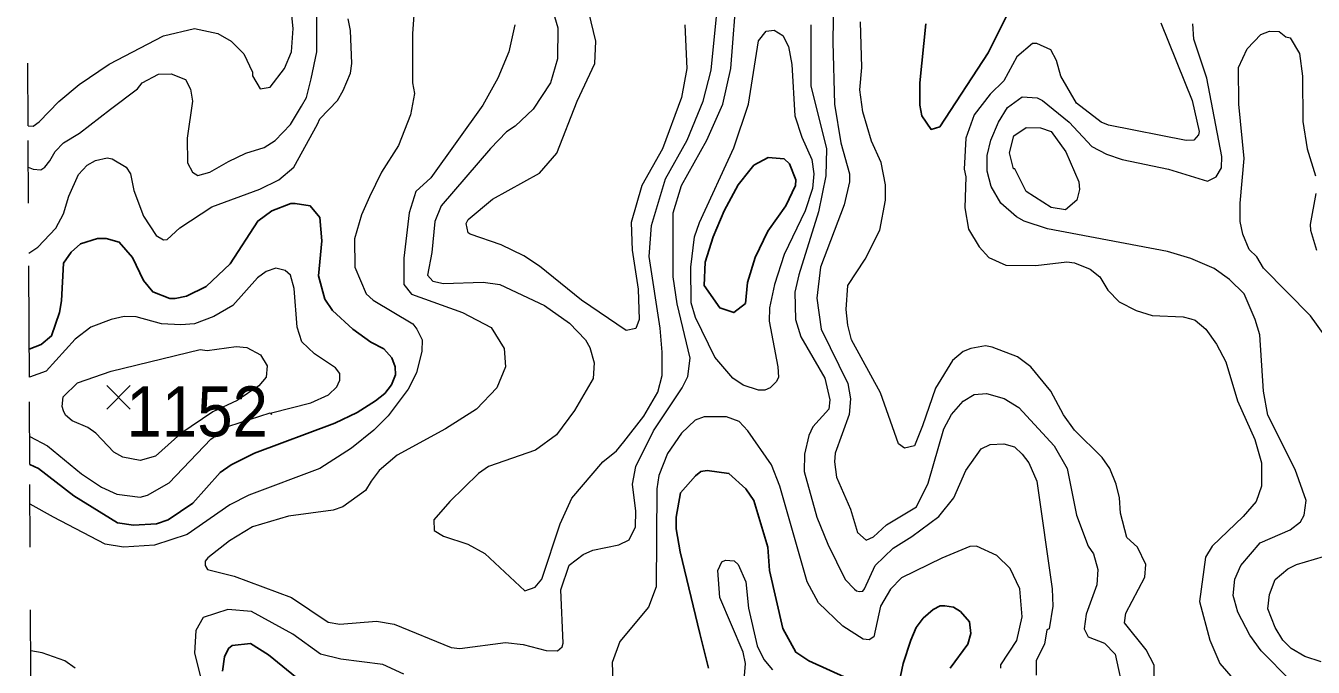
# Model space of a CAD drawing. Extents: x 423 to 448.8, y 7456.3 to 7484.
# Drawn here: x 423.048 to 425.103, y 7471.525 to 7472.549 of the extents above; entities that cross this region are included whole.
import ezdxf
from ezdxf.enums import TextEntityAlignment as Align

# ---------------------------------------------------------------- set-up
doc = ezdxf.new("R2010")
doc.units = 0
doc.header["$LTSCALE"] = 0.032
doc.linetypes.add('SHORT_DASHED', pattern=[2.7, 1.5, -1.2])
for name, color, linetype, lineweight in [('1', 7, 'Continuous', 25), ('2', 7, 'Continuous', 13), ('21', 7, 'Continuous', 25), ('22', 7, 'SHORT_DASHED', 13)]:
    doc.layers.add(name, color=color, linetype=linetype, lineweight=lineweight)
doc.layers.add('61', color=7, linetype='Continuous')

msp = doc.modelspace()

# ---------------------------------------------------------------- linework, layer by layer
at = {"layer": '1'}
for points in [[(424.6197, 7472.5766), (424.5841, 7472.5054), (424.5067, 7472.3871), (424.4928, 7472.3832), (424.4781, 7472.4049), (424.475, 7472.4219), (424.475, 7472.4575), (424.4843, 7472.5518)], [(423.0536, 7472.0326), (423.0727, 7472.0398), (423.089, 7472.0537), (423.1021, 7472.0908), (423.1052, 7472.1094), (423.1083, 7472.1697), (423.1207, 7472.1875), (423.1354, 7472.2006), (423.1625, 7472.2091), (423.1764, 7472.2091), (423.1973, 7472.203), (423.2181, 7472.179), (423.2359, 7472.1419), (423.2506, 7472.1241), (423.2777, 7472.1132), (423.2862, 7472.1132), (423.3048, 7472.1171), (423.3357, 7472.1326), (423.3744, 7472.1689), (423.4185, 7472.237), (423.4409, 7472.2533), (423.4711, 7472.2648), (423.478, 7472.2648), (423.502, 7472.261), (423.5175, 7472.2424), (423.5206, 7472.2053), (423.5152, 7472.1496), (423.5252, 7472.1125), (423.5376, 7472.0939), (423.5701, 7472.0645), (423.5987, 7472.0436), (423.6196, 7472.0328), (423.6322, 7472.0188), (423.6373, 7472.0042), (423.6382, 7471.9913), (423.6319, 7471.9756), (423.6211, 7471.9617), (423.6064, 7471.95), (423.5771, 7471.9315), (423.5415, 7471.9145), (423.4131, 7471.8665), (423.376, 7471.848), (423.3581, 7471.8356), (423.3148, 7471.7868), (423.2754, 7471.7598), (423.2568, 7471.7536), (423.2197, 7471.7513), (423.1942, 7471.7551), (423.1246, 7471.7985), (423.0681, 7471.8418), (423.0545, 7471.8482)], [(424.2321, 7471.7165), (424.2097, 7471.7907), (424.1973, 7471.8093), (424.1703, 7471.834), (424.1355, 7471.8387), (424.1254, 7471.8371), (424.1169, 7471.8302), (424.0929, 7471.8031), (424.086, 7471.7644), (424.086, 7471.7459), (424.0922, 7471.7088), (424.1238, 7471.5788), (424.1378, 7471.5231)], [(424.3598, 7471.5069), (424.2979, 7471.5347), (424.277, 7471.5486), (424.2561, 7471.5866), (424.2352, 7471.6794), (424.2321, 7471.7165)], [(424.523, 7471.5231), (424.5516, 7471.5618), (424.5562, 7471.5788), (424.5539, 7471.5974), (424.54, 7471.6136), (424.5284, 7471.6206), (424.5145, 7471.6229), (424.5075, 7471.6229), (424.4959, 7471.6167), (424.4804, 7471.6028), (424.4688, 7471.5881), (424.4603, 7471.568), (424.448, 7471.5309), (424.4379, 7471.4829)], [(423.5012, 7471.4906), (423.4355, 7471.5447), (423.4069, 7471.5626), (423.3775, 7471.5594), (423.3713, 7471.5548), (423.3651, 7471.5416), (423.362, 7471.5185)]]:
    msp.add_lwpolyline(points, dxfattribs=at)
msp.add_lwpolyline([(424.2035, 7472.3182), (424.2097, 7472.326), (424.2329, 7472.3383), (424.2584, 7472.336), (424.267, 7472.3283), (424.277, 7472.3028), (424.2762, 7472.2935), (424.2608, 7472.261), (424.2321, 7472.2208), (424.212, 7472.179), (424.1997, 7472.1388), (424.1966, 7472.1055), (424.178, 7472.0908), (424.1556, 7472.0986), (424.1308, 7472.1341), (424.1324, 7472.1713), (424.1448, 7472.2115), (424.1625, 7472.2533), (424.185, 7472.295)], close=True, dxfattribs=at)
at = {"layer": '2'}
for points in [[(423.0517, 7472.3891), (423.0596, 7472.3886), (423.0696, 7472.3955), (423.1006, 7472.428), (423.133, 7472.4551), (423.181, 7472.4876), (423.2677, 7472.5325), (423.3172, 7472.5441), (423.3543, 7472.5363), (423.376, 7472.524), (423.396, 7472.5039), (423.4099, 7472.4745), (423.4099, 7472.469), (423.4223, 7472.4481), (423.4378, 7472.4505), (423.461, 7472.4807), (423.4719, 7472.507), (423.4749, 7472.5441), (423.4657, 7472.6338)], [(423.8787, 7472.6091), (423.8973, 7472.5456), (423.8965, 7472.4961), (423.8856, 7472.4575), (423.8578, 7472.4157), (423.8292, 7472.3886), (423.8152, 7472.3793), (423.7897, 7472.353), (423.7108, 7472.261), (423.7008, 7472.2363), (423.6962, 7472.1868), (423.6892, 7472.1504), (423.6977, 7472.1411), (423.7147, 7472.1372), (423.7782, 7472.1396), (423.8044, 7472.1357), (423.8756, 7472.1024), (423.9158, 7472.0738), (423.9413, 7472.0475), (423.9483, 7472.0352), (423.9552, 7472.0104), (423.9537, 7471.9857), (423.9235, 7471.9346), (423.8949, 7471.8959), (423.8617, 7471.8711), (423.7866, 7471.8449), (423.7704, 7471.8341), (423.7248, 7471.7891), (423.6993, 7471.7598), (423.7, 7471.7428), (423.7147, 7471.7342), (423.7534, 7471.7211), (423.7805, 7471.7064), (423.8446, 7471.6468), (423.8609, 7471.6523), (423.8717, 7471.6654), (423.9011, 7471.7536), (423.9197, 7471.7946), (423.9692, 7471.8526), (423.9908, 7471.8704), (424.0024, 7471.8843), (424.0342, 7471.9253), (424.0566, 7471.964), (424.0635, 7471.9903), (424.0635, 7472.0274)], [(423.8787, 7471.5517), (423.8965, 7471.551), (423.9042, 7471.5572), (423.9057, 7471.5633), (423.9019, 7471.6484), (423.915, 7471.6879), (423.9375, 7471.7049), (423.953, 7471.7118), (423.9947, 7471.7203), (424.0109, 7471.7281), (424.021, 7471.7489), (424.0218, 7471.7737), (424.0164, 7471.817), (424.0218, 7471.8449), (424.0496, 7471.9021), (424.0953, 7471.9709), (424.1045, 7471.9887), (424.1084, 7472.0181), (424.0875, 7472.1048), (424.0813, 7472.1481), (424.0813, 7472.2502), (424.0945, 7472.2935), (424.1347, 7472.3662), (424.1602, 7472.4234), (424.1734, 7472.4807), (424.1834, 7472.6106)], [(424.0635, 7472.0274), (424.0604, 7472.0661), (424.0427, 7472.1806), (424.0465, 7472.2301), (424.0689, 7472.3043), (424.1037, 7472.3662), (424.1293, 7472.4281), (424.1417, 7472.4776), (424.154, 7472.6013)], [(424.3373, 7472.5967), (424.3358, 7472.5224), (424.3389, 7472.4234), (424.3489, 7472.3616), (424.3628, 7472.3121), (424.3628, 7472.2997), (424.3543, 7472.2626), (424.3164, 7472.1636), (424.3103, 7472.114), (424.3172, 7472.0645), (424.3598, 7471.9779), (424.3644, 7471.9532), (424.3621, 7471.9284), (424.3396, 7471.8665), (424.3389, 7471.8526), (424.342, 7471.8279), (424.3644, 7471.7768), (424.3753, 7471.7396), (424.3892, 7471.7273), (424.4008, 7471.7327), (424.4217, 7471.752), (424.4696, 7471.7807), (424.4881, 7471.8186), (424.5129, 7471.9052), (424.5253, 7471.9284), (424.5439, 7471.9493), (424.5616, 7471.9601), (424.581, 7471.9617), (424.6096, 7471.9539), (424.6328, 7471.9392), (424.6892, 7471.8781), (424.7101, 7471.8418), (424.7249, 7471.7675), (424.7434, 7471.718), (424.7519, 7471.7057), (424.7589, 7471.6809), (424.7573, 7471.6562), (424.7403, 7471.6097), (424.7372, 7471.5858), (424.7434, 7471.5734), (424.7697, 7471.5633), (424.7867, 7471.5455), (424.8007, 7471.4798)], [(423.0521, 7472.3228), (423.0597, 7472.3195), (423.0722, 7472.3185), (423.0783, 7472.3231), (423.0862, 7472.3331), (423.0951, 7472.3477), (423.1083, 7472.3617), (423.1336, 7472.3771), (423.1833, 7472.4156), (423.2266, 7472.4481), (423.2336, 7472.4575), (423.2599, 7472.4714), (423.28, 7472.4721), (423.3032, 7472.4629), (423.3109, 7472.4474), (423.3141, 7472.4281), (423.3055, 7472.3693), (423.3063, 7472.3298), (423.3141, 7472.3151), (423.3226, 7472.3097), (423.3419, 7472.3151), (423.3713, 7472.3322), (423.3992, 7472.3453), (423.4285, 7472.3546), (423.4463, 7472.3654), (423.4703, 7472.3909), (423.4881, 7472.4203), (423.4958, 7472.4343), (423.5035, 7472.4637), (423.5128, 7472.507), (423.5128, 7472.5766)], [(423.6683, 7472.5804), (423.6652, 7472.5364), (423.6652, 7472.4575), (423.6683, 7472.4405), (423.6621, 7472.4064), (423.6428, 7472.3577), (423.6157, 7472.3151), (423.5964, 7472.2757), (423.584, 7472.2471), (423.5724, 7472.2084), (423.5732, 7472.1636), (423.591, 7472.121), (423.6026, 7472.1109), (423.666, 7472.073), (423.6722, 7472.0645), (423.6807, 7472.0475), (423.6799, 7472.029), (423.6714, 7471.9949), (423.6582, 7471.9686), (423.6265, 7471.9261), (423.6034, 7471.9029), (423.5677, 7471.8742), (423.5175, 7471.8418), (423.4038, 7471.7992), (423.3736, 7471.7838), (423.3055, 7471.7366), (423.2537, 7471.7196), (423.2042, 7471.7165), (423.1749, 7471.7211), (423.0921, 7471.7644), (423.0549, 7471.785)], [(423.0528, 7472.1859), (423.0673, 7472.1952), (423.0959, 7472.2254), (423.1083, 7472.2486), (423.1168, 7472.2765), (423.1323, 7472.3113), (423.1462, 7472.3259), (423.1594, 7472.3337), (423.1779, 7472.3376), (423.1857, 7472.336), (423.2081, 7472.3229), (423.215, 7472.3121), (423.2205, 7472.2857), (423.2359, 7472.2447), (423.256, 7472.2138), (423.2677, 7472.2068), (423.2739, 7472.2076), (423.294, 7472.2262), (423.345, 7472.2595), (423.4216, 7472.288), (423.4517, 7472.3027), (423.4757, 7472.3228), (423.5136, 7472.3917), (423.5175, 7472.4002), (423.5453, 7472.4296), (423.5546, 7472.4451), (423.5662, 7472.4729), (423.5685, 7472.4884), (423.5662, 7472.541), (423.5623, 7472.5596)], [(423.9351, 7472.1109), (423.8679, 7472.1651), (423.8431, 7472.1813), (423.8067, 7472.1991), (423.7572, 7472.2161), (423.7541, 7472.2184), (423.751, 7472.2331), (423.7541, 7472.2394), (423.7928, 7472.2718), (423.8678, 7472.3136), (423.8957, 7472.3453), (423.9282, 7472.4281), (423.956, 7472.4884), (423.9576, 7472.524), (423.9467, 7472.5704)], [(424.8053, 7471.7319), (424.7952, 7471.7706), (424.7937, 7471.7954), (424.7883, 7471.817), (424.7782, 7471.8418), (424.7658, 7471.8596), (424.7218, 7471.9029), (424.704, 7471.9276), (424.6839, 7471.9655), (424.6521, 7472.0042), (424.6305, 7472.0204), (424.5903, 7472.0359), (424.5795, 7472.0375), (424.5563, 7472.0336), (424.5439, 7472.0289), (424.5269, 7472.0142), (424.4998, 7471.9702), (424.4789, 7471.9099), (424.4665, 7471.8781), (424.4503, 7471.8743), (424.441, 7471.8812), (424.4123, 7471.9625), (424.366, 7472.0475), (424.3598, 7472.0707), (424.3574, 7472.0955), (424.3598, 7472.1341), (424.3876, 7472.1759), (424.4108, 7472.2223), (424.4201, 7472.2703), (424.4201, 7472.295), (424.4131, 7472.3306), (424.3977, 7472.3647), (424.3837, 7472.4111), (424.3791, 7472.4466), (424.3822, 7472.4822), (424.3799, 7472.5549)], [(423.8284, 7472.5503), (423.8191, 7472.507), (423.8013, 7472.4652), (423.7773, 7472.4219), (423.6946, 7472.3058), (423.6706, 7472.2842), (423.6598, 7472.2502), (423.6513, 7472.1775), (423.6513, 7472.1357), (423.6636, 7472.1202), (423.7449, 7472.0908), (423.7905, 7472.0668), (423.8114, 7472.0336), (423.8137, 7472.0042), (423.7998, 7471.9709), (423.7673, 7471.9369), (423.7178, 7471.9052), (423.6405, 7471.8634), (423.6118, 7471.8387), (423.5995, 7471.8217), (423.5902, 7471.807), (423.5538, 7471.7807), (423.5384, 7471.7752), (423.4672, 7471.766), (423.41, 7471.7489), (423.3729, 7471.7265), (423.3388, 7471.6995), (423.3342, 7471.6943), (423.3342, 7471.687), (423.338, 7471.6809), (423.3806, 7471.6701), (423.4719, 7471.636), (423.5306, 7471.5966), (423.5492, 7471.5935), (423.608, 7471.5981), (423.6358, 7471.5935), (423.7271, 7471.5564), (423.741, 7471.5548), (423.8137, 7471.5641), (423.8416, 7471.561), (423.8787, 7471.5517)], [(424.0999, 7472.5503), (424.103, 7472.4807), (424.0945, 7472.4343), (424.0643, 7472.3523), (424.031, 7472.2935), (424.014, 7472.2347), (424.0156, 7472.1906), (424.0256, 7472.128), (424.0272, 7472.08), (424.0218, 7472.0653), (424.0063, 7472.0622), (423.9351, 7472.1109)], [(424.301, 7472.5503), (424.301, 7472.4528), (424.3258, 7472.3523), (424.325, 7472.309), (424.3134, 7472.2517), (424.2816, 7472.1512), (424.2755, 7472.1233), (424.2762, 7472.08), (424.2847, 7472.0522), (424.3234, 7471.9864), (424.3311, 7471.9516), (424.3296, 7471.9369), (424.3041, 7471.9083), (424.2979, 7471.8944), (424.2909, 7471.865), (424.2902, 7471.8372), (424.3103, 7471.7644), (424.328, 7471.7211), (424.3559, 7471.6646), (424.3706, 7471.6492), (424.3736, 7471.6466), (424.3785, 7471.6455), (424.3837, 7471.6462), (424.3868, 7471.6499), (424.4038, 7471.6871), (424.4325, 7471.7149), (424.4619, 7471.7335), (424.5052, 7471.7652), (424.5292, 7471.7954), (424.5485, 7471.8387), (424.5725, 7471.8735), (424.5871, 7471.8805), (424.6088, 7471.8812), (424.6259, 7471.8766), (424.6382, 7471.865), (424.649, 7471.8511), (424.6614, 7471.8217), (424.6862, 7471.65), (424.6869, 7471.6221), (424.6815, 7471.5858), (424.6777, 7471.5842), (424.6738, 7471.5618), (424.6606, 7471.5355), (424.6606, 7471.5123)], [(424.8594, 7472.5534), (424.9097, 7472.4296), (424.9205, 7472.3801), (424.9198, 7472.3747), (424.912, 7472.3662), (424.8997, 7472.3654), (424.7759, 7472.3901), (424.7643, 7472.3948), (424.7249, 7472.4249), (424.7001, 7472.4683), (424.6931, 7472.493), (424.6838, 7472.51), (424.6614, 7472.5201), (424.6545, 7472.5201), (424.6297, 7472.4992), (424.6088, 7472.4606), (424.5871, 7472.4397), (424.5616, 7472.4064), (424.5485, 7472.3693), (424.5454, 7472.3198), (424.5485, 7472.3074), (424.5469, 7472.2579), (424.5524, 7472.2239), (424.5694, 7472.196), (424.5848, 7472.179), (424.6119, 7472.1666), (424.6599, 7472.1658), (424.7094, 7472.172), (424.7218, 7472.1705), (424.7465, 7472.1604), (424.762, 7472.148), (424.7751, 7472.1264), (424.7929, 7472.1079), (424.82, 7472.0939), (424.8455, 7472.0862), (424.895, 7472.0839), (424.9074, 7472.0808), (424.9144, 7472.0785), (424.9314, 7472.0645), (424.9484, 7472.0405), (424.9631, 7472.012), (424.9817, 7471.9501), (425.0095, 7471.8882), (425.0203, 7471.8511), (425.0203, 7471.8139), (425.0118, 7471.7892), (424.9909, 7471.7652), (424.9414, 7471.718), (424.9306, 7471.7002), (424.9213, 7471.6299), (424.9375, 7471.568), (424.9538, 7471.5309), (424.9747, 7471.5061)], [(425.0667, 7471.503), (425.0195, 7471.551), (425.0017, 7471.5757), (424.9824, 7471.6128), (424.9771, 7471.6316), (424.9747, 7471.6391), (424.9778, 7471.6654), (424.987, 7471.6871), (425.018, 7471.7234), (425.0659, 7471.7443), (425.0822, 7471.7567), (425.0884, 7471.7675), (425.0914, 7471.7907), (425.0737, 7471.8402), (425.0304, 7471.9269), (425.0234, 7471.9655), (425.0172, 7472.0553), (425.0102, 7472.08), (424.9925, 7472.121), (424.9693, 7472.1434), (424.9445, 7472.1612), (424.9074, 7472.1774), (424.8703, 7472.1883), (424.6785, 7472.2246), (424.6413, 7472.237), (424.6289, 7472.2439), (424.6042, 7472.2656), (424.5887, 7472.2919), (424.5825, 7472.3167), (424.5825, 7472.3414), (424.5879, 7472.3662), (424.6003, 7472.3948), (424.615, 7472.418), (424.6382, 7472.435), (424.6622, 7472.4335), (424.6707, 7472.4296), (424.7133, 7472.3948), (424.7496, 7472.3561), (424.7728, 7472.3437), (424.7976, 7472.3352), (424.8718, 7472.3198), (424.9337, 7472.3004), (424.9476, 7472.3074), (424.9561, 7472.3221), (424.9569, 7472.3399), (424.9329, 7472.4652), (424.912, 7472.5271), (424.9105, 7472.5518)], [(425.1324, 7472.0383), (425.0984, 7472.0854), (425.0234, 7472.162), (425.0126, 7472.1798), (425.0002, 7472.1913), (424.9902, 7472.2161), (424.9863, 7472.2363), (424.9863, 7472.2656), (424.9925, 7472.3368), (424.9839, 7472.4234), (424.9832, 7472.4822), (424.9971, 7472.5116), (425.0188, 7472.5348), (425.0327, 7472.5402), (425.0481, 7472.5394), (425.059, 7472.5309), (425.0659, 7472.5294), (425.0806, 7472.5046), (425.0853, 7472.4683), (425.086, 7472.3956), (425.093, 7472.3523), (425.1062, 7472.309)], [(425.107, 7472.2811), (425.0977, 7472.2316), (425.0984, 7472.2223), (425.1077, 7472.1906)], [(423.0543, 7471.893), (423.0828, 7471.8781), (423.1369, 7471.8333), (423.1687, 7471.8124), (423.1934, 7471.8008), (423.2305, 7471.7961), (423.2421, 7471.7992), (423.2769, 7471.8193), (423.3435, 7471.8889), (423.372, 7471.9093), (423.4381, 7471.931), (423.4401, 7471.9284), (423.4401, 7471.9307), (423.5028, 7471.9469), (423.5314, 7471.9593), (423.5445, 7471.9725), (423.5487, 7471.9821), (423.549, 7471.9821), (423.5492, 7471.9934), (423.5422, 7472.0026), (423.5089, 7472.0251), (423.4888, 7472.0444), (423.4811, 7472.0676), (423.4765, 7472.1295), (423.4703, 7472.1504), (423.4618, 7472.1581), (423.4471, 7472.162), (423.4316, 7472.1566), (423.4177, 7472.1465), (423.3783, 7472.1024), (423.3481, 7472.0847), (423.3172, 7472.073), (423.2955, 7472.0715), (423.2646, 7472.073), (423.2244, 7472.0839), (423.205, 7472.0847), (423.1841, 7472.08), (423.1516, 7472.0676), (423.1269, 7472.0483), (423.0804, 7471.9972), (423.0538, 7471.9875)], [(424.6042, 7471.5231), (424.6042, 7471.5285), (424.6297, 7471.5672), (424.6382, 7471.6051), (424.6343, 7471.65), (424.6189, 7471.6825), (424.598, 7471.7033), (424.5655, 7471.718), (424.5547, 7471.7172), (424.5098, 7471.6987), (424.4456, 7471.6677), (424.4279, 7471.6492), (424.4123, 7471.6221), (424.4015, 7471.5734), (424.3938, 7471.5687), (424.3845, 7471.5695), (424.352, 7471.5904), (424.3133, 7471.6275), (424.2948, 7471.6608), (424.2515, 7471.8139), (424.2383, 7471.848), (424.2004, 7471.9021), (424.1865, 7471.9168), (424.1664, 7471.9245), (424.1308, 7471.9245), (424.1161, 7471.9191), (424.0945, 7471.8982), (424.072, 7471.8657), (424.0581, 7471.831), (424.055, 7471.8093), (424.0542, 7471.6531), (424.0419, 7471.6206), (423.9963, 7471.5656), (423.9839, 7471.5324), (423.9854, 7471.4852)], [(424.8486, 7471.4783), (424.8486, 7471.5278), (424.8362, 7471.5525), (424.8014, 7471.5958), (424.8038, 7471.6113), (424.8339, 7471.6685), (424.8354, 7471.6886), (424.8223, 7471.7164), (424.8053, 7471.7319)], [(424.1943, 7471.5046), (424.1966, 7471.5308), (424.1927, 7471.5486), (424.1556, 7471.6361), (424.1525, 7471.6794), (424.1587, 7471.6932), (424.1649, 7471.6956), (424.1788, 7471.6948), (424.185, 7471.6886), (424.1974, 7471.6608), (424.2012, 7471.619), (424.2151, 7471.5587), (424.226, 7471.537), (424.2399, 7471.5208)], [(425.1154, 7471.5331), (425.0891, 7471.5417), (425.0675, 7471.5548), (425.0543, 7471.568), (425.042, 7471.5881), (425.0304, 7471.6182), (425.0327, 7471.6407), (425.0419, 7471.6646), (425.0621, 7471.6817), (425.076, 7471.6886), (425.1333, 7471.7056)], [(423.6513, 7471.5138), (423.618, 7471.5293), (423.5508, 7471.5378), (423.5183, 7471.5455), (423.4742, 7471.5773), (423.4084, 7471.6136), (423.3705, 7471.6167), (423.331, 7471.6043), (423.3195, 7471.5835), (423.3172, 7471.5471), (423.3326, 7471.486)], [(423.1269, 7471.5231), (423.1106, 7471.5347), (423.0743, 7471.5479), (423.0561, 7471.551)]]:
    msp.add_lwpolyline(points, dxfattribs=at)
for points in [[(424.1765, 7471.9864), (424.1478, 7472.0196), (424.1169, 7472.0831), (424.1099, 7472.1063), (424.1092, 7472.1636), (424.1154, 7472.2115), (424.1231, 7472.2347), (424.178, 7472.3538), (424.2012, 7472.4234), (424.2175, 7472.5247), (424.2298, 7472.5402), (424.2422, 7472.5417), (424.2561, 7472.5332), (424.2654, 7472.5154), (424.2708, 7472.4869), (424.2755, 7472.4049), (424.2863, 7472.3708), (424.3025, 7472.3353), (424.3056, 7472.3121), (424.3033, 7472.2889), (424.2917, 7472.2533), (424.2585, 7472.1837), (424.243, 7472.1357), (424.2352, 7472.0986), (424.2345, 7472.0769), (424.2484, 7472.0042), (424.2492, 7471.988), (424.2461, 7471.981), (424.236, 7471.9709), (424.2275, 7471.9671), (424.2175, 7471.9671), (424.1927, 7471.9748)], [(424.6266, 7472.3205), (424.6243, 7472.3205), (424.6181, 7472.3461), (424.6251, 7472.3731), (424.6444, 7472.3863), (424.6676, 7472.3855), (424.6846, 7472.3801), (424.7078, 7472.3476), (424.7287, 7472.2997), (424.7295, 7472.2873), (424.7256, 7472.2702), (424.7071, 7472.2548), (424.6846, 7472.2587), (424.6444, 7472.2842)], [(423.1601, 7471.8982), (423.147, 7471.9075), (423.1222, 7471.9183), (423.1114, 7471.9269), (423.1083, 7471.9338), (423.106, 7471.9408), (423.1075, 7471.9563), (423.1307, 7471.9787), (423.1841, 7471.9972), (423.3265, 7472.032), (423.3373, 7472.0305), (423.3837, 7472.0367), (423.4007, 7472.0352), (423.4224, 7472.0235), (423.4331, 7472.0057), (423.4316, 7471.9879), (423.42, 7471.974), (423.3855, 7471.9504), (423.3464, 7471.9324), (423.2954, 7471.8979), (423.2553, 7471.8619), (423.2305, 7471.8549), (423.2027, 7471.8603), (423.1888, 7471.868)]]:
    msp.add_lwpolyline(points, close=True, dxfattribs=at)
at = {"layer": '21'}
for p, q in [((423.1773, 7471.9743), (423.2148, 7471.9368)), ((423.2148, 7471.9743), (423.1773, 7471.9368))]:
    msp.add_line(p, q, dxfattribs=at)
at = {"layer": '22'}
for points in [[(423.0517, 7472.3891), (423.0505, 7472.6305), (423.05, 7472.7245), (423.0485, 7473.0283), (423.048, 7473.128)], [(423.0538, 7471.9875), (423.0534, 7472.0657), (423.0517, 7472.3891)], [(423.0573, 7471.3029), (423.0563, 7471.5008), (423.0562, 7471.5163), (423.0545, 7471.8482), (423.0538, 7471.9875)]]:
    msp.add_lwpolyline(points, dxfattribs=at)

# ---------------------------------------------------------------- texts
at = {"layer": '61', "width": 0.95}
msp.add_text('1152', height=0.08, dxfattribs=at).set_placement((423.3216, 7471.893), align=Align.CENTER)

doc.saveas('drawing.dxf')
